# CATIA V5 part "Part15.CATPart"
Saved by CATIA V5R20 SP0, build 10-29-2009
Part number: 8PF1242WB-00-RECTO-20130123
Revision: ANY
Definition: UNKNOWN
Nomenclature: 8PF1242WB-00-RECTO-20130123
Source: Unknown
Bounding box of the stored display mesh (mm): x 1756.119 to 1956.119, y 1406.509 to 1410.509, z 0 to 12
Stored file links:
  C:\Users\Utente\Desktop\IO LAVORO\3D X SITO CF\CUMSA\3D files PF\PF 1242WB\Part15.CATPart
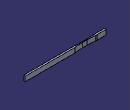
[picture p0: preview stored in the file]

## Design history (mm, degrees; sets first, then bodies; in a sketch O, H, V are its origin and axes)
Body1 "Cortar-Extruir1" (main body)
  Solid1: solid without history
